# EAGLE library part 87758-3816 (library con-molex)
38 Pin - 2mm Dual Row Single Wafer, Vertical T/H HDR Source: http://www.molex.com/pdm_docs/sd/877580616_sd.pdf
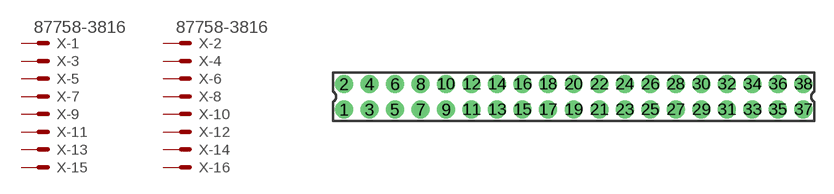
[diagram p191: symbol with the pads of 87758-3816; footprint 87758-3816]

Designator prefix X; gates -1=MV -2=MV -3=M -4=M -5=M -6=M -7=M -8=M -9=M -10=M -11=M -12=M -13=M -14=M -15=M -16=M -17=M -18=M -19=M -20=M -21=M -22=M -23=M -24=M -25=M -26=M -27=M -28=M -29=M -30=M -31=M -32=M -33=M -34=M -35=M -36=M -37=M -38=M

## 87758-3816 (MPN: 87758-3816; OC_FARNELL: unknown; OC_NEWARK: 25M5690)  [87758-3816]
1  -1:S  pas
2  -2:S  pas
3  -3:S  pas
4  -4:S  pas
5  -5:S  pas
6  -6:S  pas
7  -7:S  pas
8  -8:S  pas
9  -9:S  pas
10  -10:S  pas
11  -11:S  pas
12  -12:S  pas
13  -13:S  pas
14  -14:S  pas
15  -15:S  pas
16  -16:S  pas
17  -17:S  pas
18  -18:S  pas
19  -19:S  pas
20  -20:S  pas
21  -21:S  pas
22  -22:S  pas
23  -23:S  pas
24  -24:S  pas
25  -25:S  pas
26  -26:S  pas
27  -27:S  pas
28  -28:S  pas
29  -29:S  pas
30  -30:S  pas
31  -31:S  pas
32  -32:S  pas
33  -33:S  pas
34  -34:S  pas
35  -35:S  pas
36  -36:S  pas
37  -37:S  pas
38  -38:S  pas

## Footprint 87758-3816 (pad centres in mm)
38 Pin - 2mm Dual Row Single Wafer, Vertical T/H HDR Source: http://www.molex.com/pdm_docs/sd/877580616_sd.pdf
drill 0.9 pad 1.27 round: 1 -18,-1; 2 -18,1; 3 -16,-1; 4 -16,1; 5 -14,-1; 6 -14,1; 7 -12,-1; 8 -12,1; 9 -10,-1; 10 -10,1; 11 -8,-1; 12 -8,1; 13 -6,-1; 14 -6,1; 15 -4,-1; 16 -4,1; 17 -2,-1; 18 -2,1; 19 0,-1; 20 0,1; 21 2,-1; 22 2,1; 23 4,-1; 24 4,1; 25 6,-1; 26 6,1; 27 8,-1; 28 8,1; 29 10,-1; 30 10,1; 31 12,-1; 32 12,1; 33 14,-1; 34 14,1; 35 16,-1; 36 16,1; 37 18,-1; 38 18,1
